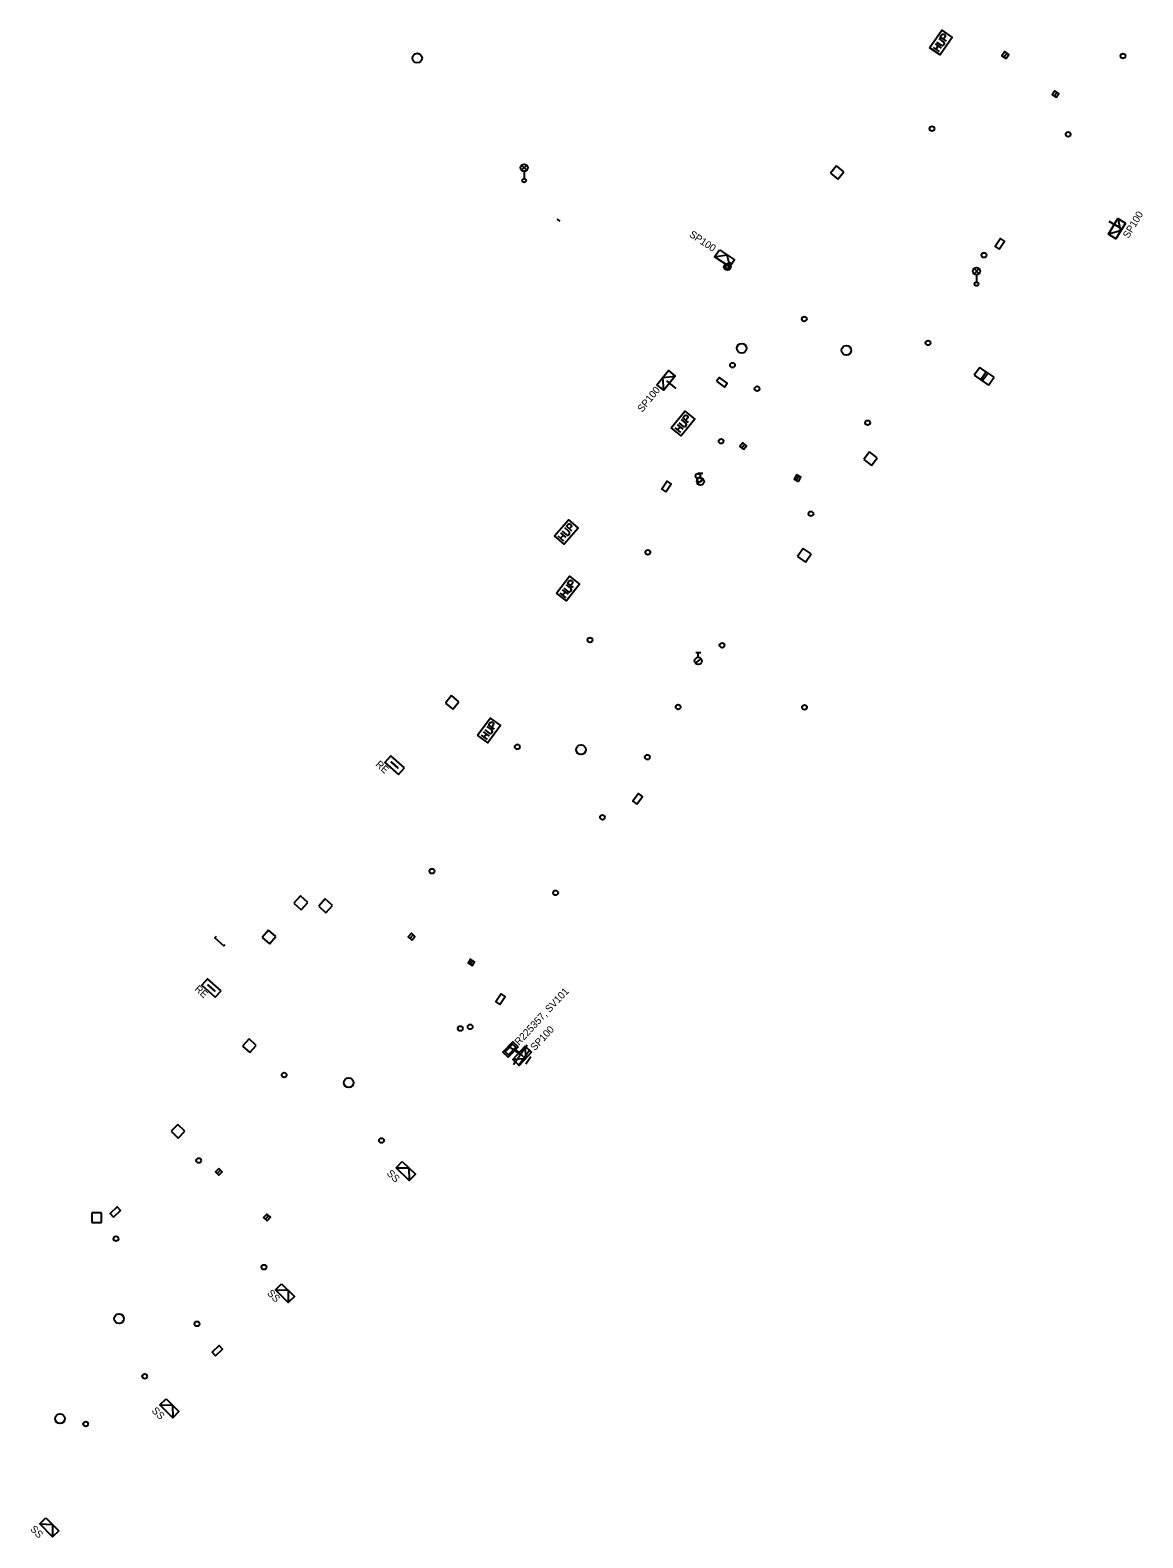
# Model space of a CAD drawing. Extents: x -577028 to -568584, y -1207664 to -1202947.
# Drawn here: x -569115.9 to -569000.9, y -1204629.8 to -1204473.9 of the extents above; entities that cross this region are included whole.
import ezdxf

# ---------------------------------------------------------------- set-up
doc = ezdxf.new("R2010")
doc.units = 0
for name, color, linetype in [('CIZÍ_NADZEM', 7, 'Continuous'), ('CIZÍ_PODZEM', 7, 'Continuous'), ('ELE_EON', 7, 'Continuous'), ('ELE_EON_POPIS', 7, 'Continuous')]:
    doc.layers.add(name, color=color, linetype=linetype)

msp = doc.modelspace()

# ---------------------------------------------------------------- linework, layer by layer
at = {"layer": 'CIZÍ_NADZEM'}
for p, q in [((-569015.22, -1204476.7), (-569014.94, -1204476.28)), ((-569010.04, -1204480.75), (-569009.76, -1204480.33)), ((-569065.09, -1204488.4), (-569064.57, -1204487.87)), ((-569064.56, -1204488.4), (-569065.09, -1204487.87)), ((-569064.83, -1204488.51), (-569064.83, -1204489.26)), ((-569032.53, -1204487.94), (-569033.17, -1204488.7)), ((-569031.77, -1204488.58), (-569032.53, -1204487.94)), ((-569032.41, -1204489.34), (-569031.77, -1204488.58)), ((-569033.17, -1204488.7), (-569032.41, -1204489.34)), ((-569018.32, -1204499.11), (-569017.8, -1204498.58)), ((-569017.79, -1204499.1), (-569018.32, -1204498.58)), ((-569018.06, -1204499.22), (-569018.06, -1204499.97)), ((-569017.71, -1204508.8), (-569018.3, -1204509.61)), ((-569016.9, -1204509.39), (-569017.71, -1204508.8)), ((-569018.3, -1204509.61), (-569017.49, -1204510.2)), ((-569017.07, -1204509.25), (-569017.63, -1204510.07)), ((-569017.63, -1204510.07), (-569016.81, -1204510.63)), ((-569017.49, -1204510.2), (-569016.9, -1204509.39)), ((-569016.25, -1204509.81), (-569017.07, -1204509.25)), ((-569016.81, -1204510.63), (-569016.25, -1204509.81)), ((-569042.35, -1204517.13), (-569042.03, -1204516.75)), ((-569029.11, -1204517.54), (-569029.72, -1204518.33)), ((-569028.32, -1204518.15), (-569029.11, -1204517.54)), ((-569028.93, -1204518.94), (-569028.32, -1204518.15)), ((-569046.86, -1204519.73), (-569046.36, -1204519.73)), ((-569046.61, -1204520.23), (-569046.61, -1204519.73)), ((-569029.72, -1204518.33), (-569028.93, -1204518.94)), ((-569046.9, -1204520.83), (-569046.31, -1204520.37)), ((-569036.69, -1204520.48), (-569036.47, -1204520.04)), ((-569035.99, -1204527.52), (-569036.56, -1204528.35)), ((-569035.16, -1204528.09), (-569035.99, -1204527.52)), ((-569036.56, -1204528.35), (-569035.73, -1204528.92)), ((-569035.73, -1204528.92), (-569035.16, -1204528.09)), ((-569047.08, -1204538.28), (-569046.58, -1204538.28)), ((-569046.83, -1204538.78), (-569046.83, -1204538.28)), ((-569047.12, -1204539.38), (-569046.53, -1204538.92)), ((-569072.35, -1204542.74), (-569072.98, -1204543.51)), ((-569071.58, -1204543.37), (-569072.35, -1204542.74)), ((-569072.98, -1204543.51), (-569072.21, -1204544.14)), ((-569072.21, -1204544.14), (-569071.58, -1204543.37)), ((-569087.96, -1204563.46), (-569088.63, -1204564.21)), ((-569087.21, -1204564.13), (-569087.96, -1204563.46)), ((-569088.63, -1204564.21), (-569087.88, -1204564.88)), ((-569087.88, -1204564.88), (-569087.21, -1204564.13)), ((-569085.4, -1204563.77), (-569086.07, -1204564.52)), ((-569086.07, -1204564.52), (-569085.32, -1204565.19)), ((-569084.65, -1204564.44), (-569085.4, -1204563.77)), ((-569085.32, -1204565.19), (-569084.65, -1204564.44)), ((-569091.25, -1204566.99), (-569091.91, -1204567.75)), ((-569091.91, -1204567.75), (-569091.15, -1204568.41)), ((-569090.49, -1204567.65), (-569091.25, -1204566.99)), ((-569091.15, -1204568.41), (-569090.49, -1204567.65)), ((-569076.64, -1204567.85), (-569076.3, -1204567.49)), ((-569070.42, -1204570.55), (-569070.16, -1204570.13)), ((-569093.28, -1204578.24), (-569093.95, -1204578.99)), ((-569093.95, -1204578.99), (-569093.2, -1204579.66)), ((-569092.53, -1204578.91), (-569093.28, -1204578.24)), ((-569093.2, -1204579.66), (-569092.53, -1204578.91)), ((-569100.64, -1204587.08), (-569101.34, -1204587.8)), ((-569101.34, -1204587.8), (-569100.62, -1204588.5)), ((-569099.92, -1204587.78), (-569100.64, -1204587.08)), ((-569100.62, -1204588.5), (-569099.92, -1204587.78)), ((-569096.23, -1204591.82), (-569096.59, -1204592.18)), ((-569108.52, -1204596.24), (-569109.52, -1204596.24)), ((-569109.52, -1204596.24), (-569109.52, -1204597.24)), ((-569108.52, -1204597.24), (-569108.52, -1204596.24)), ((-569109.52, -1204597.24), (-569108.52, -1204597.24)), ((-569091.58, -1204596.9), (-569091.26, -1204596.52))]:
    msp.add_line(p, q, dxfattribs=at)
for points in [[(-569022.91, -1204475.73), (-569021.66, -1204473.92), (-569020.58, -1204474.66), (-569021.82, -1204476.48), (-569022.91, -1204475.73)], [(-569021.81, -1204474.61), (-569021.65, -1204474.38), (-569021.57, -1204474.32), (-569021.52, -1204474.32), (-569021.44, -1204474.33), (-569021.35, -1204474.4), (-569021.31, -1204474.46), (-569021.3, -1204474.51), (-569021.32, -1204474.61), (-569021.48, -1204474.84)], [(-569021.18, -1204475.05), (-569021.81, -1204474.61)], [(-569022.56, -1204475.7), (-569021.93, -1204476.14)], [(-569021.68, -1204475.77), (-569022.31, -1204475.34)], [(-569022.26, -1204475.91), (-569022.01, -1204475.54)], [(-569022.19, -1204475.16), (-569021.73, -1204475.47), (-569021.62, -1204475.51), (-569021.53, -1204475.49), (-569021.44, -1204475.44), (-569021.41, -1204475.39), (-569021.38, -1204475.29), (-569021.41, -1204475.19), (-569021.48, -1204475.11), (-569021.93, -1204474.79)], [(-569049.62, -1204515.03), (-569048.23, -1204513.32), (-569047.2, -1204514.16), (-569048.6, -1204515.86), (-569049.62, -1204515.03)], [(-569049.27, -1204515.03), (-569048.67, -1204515.52)], [(-569048.39, -1204515.18), (-569048.99, -1204514.69)], [(-569048.98, -1204515.26), (-569048.71, -1204514.92)], [(-569048.85, -1204514.52), (-569048.42, -1204514.87), (-569048.32, -1204514.91), (-569048.22, -1204514.91), (-569048.13, -1204514.86), (-569048.09, -1204514.81), (-569048.06, -1204514.71), (-569048.08, -1204514.62), (-569048.14, -1204514.53), (-569048.57, -1204514.18)], [(-569048.43, -1204514.01), (-569048.25, -1204513.79), (-569048.16, -1204513.74), (-569048.12, -1204513.74), (-569048.04, -1204513.76), (-569047.95, -1204513.83), (-569047.92, -1204513.9), (-569047.91, -1204513.95), (-569047.94, -1204514.04), (-569048.12, -1204514.26)], [(-569047.83, -1204514.5), (-569048.43, -1204514.01)], [(-569061.7, -1204526.2), (-569060.24, -1204524.55), (-569059.25, -1204525.42), (-569060.71, -1204527.08), (-569061.7, -1204526.2)], [(-569060.48, -1204526.4), (-569061.05, -1204525.89)], [(-569060.91, -1204525.72), (-569060.5, -1204526.09), (-569060.39, -1204526.14), (-569060.29, -1204526.13), (-569060.2, -1204526.09), (-569060.16, -1204526.04), (-569060.13, -1204525.95), (-569060.14, -1204525.85), (-569060.2, -1204525.76), (-569060.62, -1204525.39)], [(-569060.47, -1204525.23), (-569060.28, -1204525.01), (-569060.2, -1204524.97), (-569060.15, -1204524.97), (-569060.07, -1204524.99), (-569059.99, -1204525.07), (-569059.96, -1204525.14), (-569059.95, -1204525.19), (-569059.98, -1204525.28), (-569060.17, -1204525.49)], [(-569059.9, -1204525.74), (-569060.47, -1204525.23)], [(-569061.35, -1204526.22), (-569060.77, -1204526.73)], [(-569061.07, -1204526.46), (-569060.78, -1204526.13)], [(-569061.5, -1204532.15), (-569060.16, -1204530.4), (-569059.11, -1204531.21), (-569060.45, -1204532.95), (-569061.5, -1204532.15)], [(-569061.14, -1204532.14), (-569060.53, -1204532.61)], [(-569060.26, -1204532.26), (-569060.88, -1204531.79)], [(-569060.86, -1204532.36), (-569060.59, -1204532.01)], [(-569060.74, -1204531.62), (-569060.31, -1204531.96), (-569060.2, -1204532), (-569060.1, -1204531.99), (-569060.02, -1204531.94), (-569059.98, -1204531.89), (-569059.95, -1204531.79), (-569059.97, -1204531.69), (-569060.04, -1204531.6), (-569060.47, -1204531.27)], [(-569060.34, -1204531.1), (-569060.17, -1204530.87), (-569060.08, -1204530.82), (-569060.03, -1204530.81), (-569059.96, -1204530.83), (-569059.87, -1204530.9), (-569059.83, -1204530.97), (-569059.82, -1204531.02), (-569059.85, -1204531.11), (-569060.02, -1204531.34)], [(-569059.73, -1204531.56), (-569060.34, -1204531.1)], [(-569069.64, -1204546.84), (-569068.35, -1204545.06), (-569067.28, -1204545.84), (-569068.58, -1204547.62), (-569069.64, -1204546.84)], [(-569068.9, -1204546.29), (-569068.46, -1204546.62), (-569068.35, -1204546.66), (-569068.25, -1204546.64), (-569068.17, -1204546.59), (-569068.13, -1204546.54), (-569068.11, -1204546.44), (-569068.13, -1204546.35), (-569068.2, -1204546.26), (-569068.64, -1204545.93)], [(-569068.51, -1204545.76), (-569068.35, -1204545.53), (-569068.26, -1204545.47), (-569068.21, -1204545.47), (-569068.14, -1204545.49), (-569068.05, -1204545.55), (-569068.01, -1204545.62), (-569068, -1204545.67), (-569068.02, -1204545.76), (-569068.19, -1204545.99)], [(-569067.89, -1204546.21), (-569068.51, -1204545.76)], [(-569069.29, -1204546.82), (-569068.67, -1204547.28)], [(-569068.41, -1204546.92), (-569069.03, -1204546.47)], [(-569069, -1204547.04), (-569068.74, -1204546.68)], [(-569096.67, -1204567.65), (-569096.8, -1204567.8), (-569095.88, -1204568.62), (-569095.75, -1204568.47)]]:
    msp.add_lwpolyline(points, dxfattribs=at)
for points in [[(-569015.01, -1204476.84), (-569014.73, -1204476.42), (-569015.15, -1204476.14), (-569015.43, -1204476.56)], [(-569009.83, -1204480.89), (-569009.55, -1204480.47), (-569009.97, -1204480.19), (-569010.25, -1204480.61)], [(-569015.72, -1204496.57), (-569015.17, -1204495.74), (-569015.58, -1204495.47), (-569016.13, -1204496.3)], [(-569044.93, -1204510.22), (-569044.13, -1204510.83), (-569043.83, -1204510.44), (-569044.63, -1204509.83)], [(-569042.15, -1204517.29), (-569041.84, -1204516.9), (-569042.23, -1204516.59), (-569042.54, -1204516.98)], [(-569050.19, -1204521.65), (-569049.62, -1204520.83), (-569050.03, -1204520.55), (-569050.6, -1204521.37)], [(-569036.47, -1204520.6), (-569036.24, -1204520.15), (-569036.69, -1204519.92), (-569036.92, -1204520.37)], [(-569053.18, -1204553.97), (-569052.59, -1204553.17), (-569053, -1204552.87), (-569053.59, -1204553.67)], [(-569076.46, -1204568.02), (-569076.12, -1204567.66), (-569076.48, -1204567.32), (-569076.82, -1204567.68)], [(-569070.2, -1204570.68), (-569069.95, -1204570.26), (-569070.37, -1204570), (-569070.63, -1204570.42)], [(-569067.34, -1204574.67), (-569066.78, -1204573.84), (-569067.2, -1204573.57), (-569067.76, -1204574.4)], [(-569096.41, -1204591.65), (-569096.76, -1204592), (-569096.41, -1204592.35), (-569096.06, -1204592)], [(-569107.29, -1204596.67), (-569106.56, -1204595.98), (-569106.91, -1204595.61), (-569107.64, -1204596.3)], [(-569091.39, -1204597.06), (-569091.07, -1204596.69), (-569091.44, -1204596.36), (-569091.77, -1204596.73)], [(-569096.74, -1204611.01), (-569096.02, -1204610.32), (-569096.36, -1204609.95), (-569097.08, -1204610.64)]]:
    msp.add_lwpolyline(points, close=True, dxfattribs=at)
for centre, radius in [((-569075.89, -1204476.81), 0.5), ((-569002.92, -1204476.59), 0.25), ((-569022.66, -1204484.1), 0.25), ((-569008.59, -1204484.69), 0.25), ((-569064.83, -1204488.14), 0.375), ((-569064.83, -1204489.46), 0.2), ((-569017.29, -1204497.19), 0.25), ((-569018.06, -1204498.84), 0.375), ((-569018.06, -1204500.17), 0.2), ((-569035.87, -1204503.78), 0.25), ((-569042.35, -1204506.81), 0.5), ((-569031.51, -1204507.03), 0.5), ((-569023.07, -1204506.26), 0.25), ((-569043.29, -1204508.56), 0.25), ((-569040.75, -1204511), 0.25), ((-569029.32, -1204514.52), 0.25), ((-569044.47, -1204516.43), 0.25), ((-569046.86, -1204520.02), 0.25), ((-569046.61, -1204520.6), 0.375), ((-569046.71, -1204520.41), 0.25), ((-569035.18, -1204523.93), 0.25), ((-569052.04, -1204527.92), 0.25), ((-569058.02, -1204536.98), 0.25), ((-569044.37, -1204537.53), 0.25), ((-569046.83, -1204539.15), 0.375), ((-569048.91, -1204543.91), 0.25), ((-569035.85, -1204543.95), 0.25), ((-569065.53, -1204548.04), 0.25), ((-569058.95, -1204548.34), 0.5), ((-569052.09, -1204549.11), 0.25), ((-569056.74, -1204555.32), 0.25), ((-569074.36, -1204560.89), 0.25), ((-569061.58, -1204563.14), 0.25), ((-569071.43, -1204577.16), 0.25), ((-569070.42, -1204577), 0.25), ((-569089.64, -1204581.98), 0.25), ((-569082.97, -1204582.78), 0.5), ((-569079.58, -1204588.75), 0.25), ((-569098.48, -1204590.82), 0.25), ((-569107.03, -1204598.91), 0.25), ((-569091.73, -1204601.85), 0.25), ((-569106.71, -1204607.17), 0.5), ((-569098.66, -1204607.71), 0.25), ((-569104.06, -1204613.14), 0.25), ((-569112.82, -1204617.53), 0.5), ((-569110.16, -1204618.07), 0.25)]:
    msp.add_circle(centre, radius, dxfattribs=at)
at = {"layer": 'CIZÍ_PODZEM'}
msp.add_lwpolyline([(-569061.46, -1204493.47), (-569061.13, -1204493.68)], dxfattribs=at)
at = {"layer": 'ELE_EON'}
for p, q in [((-569003.28, -1204494.34), (-569004.34, -1204493.7)), ((-569043.63, -1204498.1), (-569043.49, -1204497.89)), ((-569049.12, -1204510.98), (-569050.08, -1204510.2)), ((-569065.22, -1204579.87), (-569066.46, -1204579.01)), ((-569065.94, -1204580.89), (-569064.51, -1204578.84)), ((-569064.9, -1204580.11), (-569065.82, -1204579.25)), ((-569065.3, -1204580.85), (-569064.33, -1204579.45)), ((-569064.66, -1204580.81), (-569064.15, -1204580.07))]:
    msp.add_line(p, q, dxfattribs=at)
for points in [[(-569002.67, -1204493.87), (-569003.65, -1204495.48), (-569004.42, -1204495.01), (-569003.44, -1204493.41)], [(-569044.64, -1204496.62), (-569043.08, -1204497.66), (-569043.58, -1204498.41), (-569045.14, -1204497.37)], [(-569051.1, -1204510.58), (-569049.92, -1204509.12), (-569049.22, -1204509.69), (-569050.4, -1204511.15)], [(-569077.22, -1204550.21), (-569078.62, -1204548.97), (-569079.22, -1204549.64), (-569077.82, -1204550.89)], [(-569077.86, -1204550.22), (-569078.56, -1204549.6), (-569078.58, -1204549.63), (-569077.88, -1204550.25)], [(-569096.17, -1204573.26), (-569097.57, -1204572.02), (-569098.17, -1204572.69), (-569096.77, -1204573.94)], [(-569096.81, -1204573.27), (-569097.51, -1204572.65), (-569097.53, -1204572.68), (-569096.83, -1204573.3)], [(-569065.45, -1204579.05), (-569066.48, -1204580.14), (-569067.03, -1204579.63), (-569066, -1204578.54)], [(-569065.7, -1204579.09), (-569066.45, -1204579.89), (-569066.78, -1204579.59), (-569066.03, -1204578.78)], [(-569064.06, -1204579.61), (-569065.34, -1204580.98), (-569066, -1204580.37), (-569064.72, -1204578.99)], [(-569077.43, -1204590.93), (-569076.08, -1204592.23), (-569076.71, -1204592.88), (-569078.05, -1204591.58)], [(-569089.91, -1204603.56), (-569088.58, -1204604.88), (-569089.22, -1204605.52), (-569090.54, -1204604.2)], [(-569101.85, -1204615.46), (-569100.52, -1204616.78), (-569101.15, -1204617.42), (-569102.49, -1204616.1)], [(-569114.27, -1204627.78), (-569112.95, -1204629.11), (-569113.59, -1204629.75), (-569114.91, -1204628.41)]]:
    msp.add_lwpolyline(points, close=True, dxfattribs=at)
for points in [[(-569003.44, -1204493.41), (-569003.16, -1204494.68), (-569004.42, -1204495.01)], [(-569045.14, -1204497.37), (-569043.86, -1204497.14), (-569043.58, -1204498.41)], [(-569050.4, -1204511.15), (-569050.51, -1204509.85), (-569049.22, -1204509.69)], [(-569064.72, -1204578.99), (-569064.7, -1204580.29), (-569066, -1204580.37)], [(-569078.05, -1204591.58), (-569076.75, -1204591.58), (-569076.71, -1204592.88)], [(-569090.54, -1204604.2), (-569089.24, -1204604.22), (-569089.22, -1204605.52)], [(-569102.49, -1204616.1), (-569101.19, -1204616.12), (-569101.15, -1204617.42)], [(-569114.91, -1204628.41), (-569113.61, -1204628.45), (-569113.59, -1204629.75)]]:
    msp.add_lwpolyline(points, dxfattribs=at)
for radius in [0.35, 0.175]:
    msp.add_circle((-569043.82, -1204498.39), radius, dxfattribs=at)

# ---------------------------------------------------------------- texts
at = {"layer": 'ELE_EON_POPIS'}
for s, rotation, p in [('SP100', 58.8186, (-569002.35, -1204495.51)), ('SP100', 326.3259, (-569047.83, -1204495.21)), ('SP100', 50.843, (-569052.62, -1204513.49)), ('RE', 318.3019, (-569080.26, -1204549.94)), ('RE', 318.3231, (-569098.96, -1204573.16)), ('R225357, SV101', 46.9749, (-569065.36, -1204578.96)), ('SP100', 46.9749, (-569063.73, -1204579.52)), ('SS', 315.9864, (-569079.09, -1204592.22)), ('SS', 315.0867, (-569091.46, -1204604.61)), ('SS', 315.2968, (-569103.4, -1204616.75)), ('SS', 314.8017, (-569115.96, -1204629))]:
    msp.add_text(s, height=0.75, rotation=rotation, dxfattribs=at).set_placement(p)

doc.saveas('drawing.dxf')
